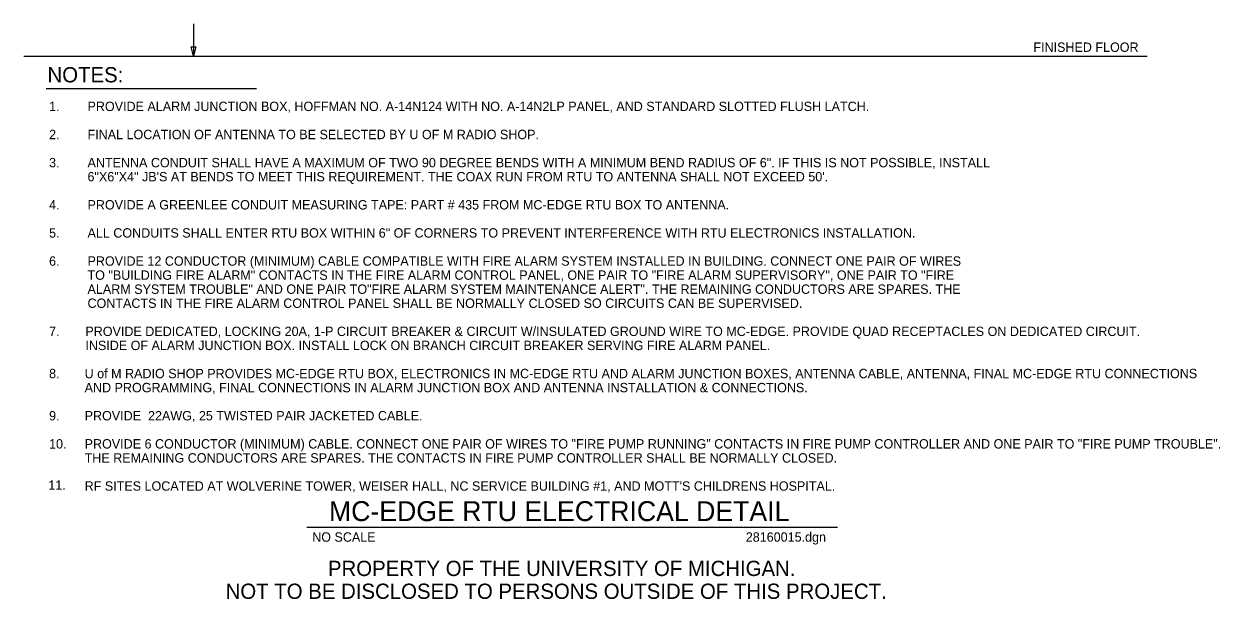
# Model space of a CAD drawing. Extents: x 10048.6 to 10135.3, y 10047.5 to 10138.5.
# Drawn here: x 10050.3 to 10135.3, y 10047.5 to 10088.4 of the extents above; entities that cross this region are included whole.
import ezdxf

# ---------------------------------------------------------------- set-up
doc = ezdxf.new("R2010")
doc.units = 0
for name, color, linetype in [('G-ANNO-CELL', 7, 'Continuous'), ('G-ANNO-TEXT', 7, 'Continuous'), ('G-DETL-PATT', 7, 'Continuous'), ('Level 3', 7, 'Continuous'), ('Level 52', 7, 'Continuous'), ('Level 60', 7, 'Continuous'), ('Level 63', 7, 'Continuous')]:
    doc.layers.add(name, color=color, linetype=linetype)

msp = doc.modelspace()

# ---------------------------------------------------------------- linework, layer by layer
at = {"layer": 'G-ANNO-CELL'}
msp.add_line((10051.862, 10083.812), (10066.824, 10083.812), dxfattribs=at)
at = {"layer": 'G-DETL-PATT'}
msp.add_line((10050.286, 10086.096), (10130.147, 10086.096), dxfattribs=at)
at = {"layer": 'Level 60'}
msp.add_line((10070.393, 10052.61), (10108.126, 10052.61), dxfattribs=at)
at = {"layer": 'Level 63'}
msp.add_line((10062.337, 10088.401), (10062.337, 10086.096), dxfattribs=at)
msp.add_lwpolyline([(10062.504, 10086.762), (10062.337, 10086.096), (10062.17, 10086.762)], close=True, dxfattribs=at)

# ---------------------------------------------------------------- texts
at = {"layer": 'G-ANNO-CELL'}
msp.add_text('NOTES: ', height=1.0833, dxfattribs=at).set_placement((10051.962, 10084.244))
at = {"layer": 'G-ANNO-TEXT'}
for s, height, p in [('PROVIDE ALARM JUNCTION BOX, HOFFMAN NO. A-14N124 WITH NO. A-14N2LP PANEL, AND STANDARD SLOTTED FLUSH LATCH.', 0.666667, (10054.808, 10082.204)), ('FINAL LOCATION OF ANTENNA TO BE SELECTED BY U OF M RADIO SHOP.', 0.66667, (10054.808, 10080.204)), ('ANTENNA CONDUIT SHALL HAVE A MAXIMUM OF TWO 90 DEGREE BENDS WITH A MINIMUM BEND RADIUS OF 6". IF THIS IS NOT POSSIBLE, INSTALL', 0.666667, (10054.808, 10078.204)), ('6"X6"X4" JB\'S AT BENDS TO MEET THIS REQUIREMENT. THE COAX RUN FROM RTU TO ANTENNA SHALL NOT EXCEED 50\'.', 0.666667, (10054.808, 10077.204)), ('PROVIDE A GREENLEE CONDUIT MEASURING TAPE: PART # 435 FROM MC-EDGE RTU BOX TO ANTENNA.', 0.66667, (10054.808, 10075.204)), ('ALL CONDUITS SHALL ENTER RTU BOX WITHIN 6" OF CORNERS TO PREVENT INTERFERENCE WITH RTU ELECTRONICS INSTALLATION.', 0.666667, (10054.808, 10073.204)), ('PROVIDE 12 CONDUCTOR (MINIMUM) CABLE COMPATIBLE WITH FIRE ALARM SYSTEM INSTALLED IN BUILDING. CONNECT ONE PAIR OF WIRES', 0.666667, (10054.808, 10071.204)), ('TO "BUILDING FIRE ALARM" CONTACTS IN THE FIRE ALARM CONTROL PANEL, ONE PAIR TO "FIRE ALARM SUPERVISORY", ONE PAIR TO "FIRE', 0.666667, (10054.808, 10070.204)), ('ALARM SYSTEM TROUBLE" AND ONE PAIR TO"FIRE ALARM SYSTEM MAINTENANCE ALERT". THE REMAINING CONDUCTORS ARE SPARES. THE', 0.666667, (10054.808, 10069.204)), ('CONTACTS IN THE FIRE ALARM CONTROL PANEL SHALL BE NORMALLY CLOSED SO CIRCUITS CAN BE SUPERVISED.', 0.66667, (10054.808, 10068.204)), ('11.', 0.6667, (10052.019, 10055.269)), ('PROPERTY OF THE UNIVERSITY OF MICHIGAN.', 1.08333, (10071.902, 10049.137)), ('NOT TO BE DISCLOSED TO PERSONS OUTSIDE OF THIS PROJECT.', 1.08333, (10064.627, 10047.512))]:
    msp.add_text(s, height=height, dxfattribs=at).set_placement(p)
at = {"layer": 'Level 3'}
msp.add_text('28160015.dgn', height=0.66667, dxfattribs=at).set_placement((10101.612, 10051.577))
at = {"layer": 'Level 52'}
msp.add_text('NO SCALE', height=0.6667, dxfattribs=at).set_placement((10070.783, 10051.575))
at = {"layer": 'Level 60'}
for s, height, p in [('FINISHED FLOOR', 0.66667, (10122.06, 10086.413)), ('PROVIDE DEDICATED, LOCKING 20A, 1-P CIRCUIT BREAKER & CIRCUIT W/INSULATED GROUND WIRE TO MC-EDGE. PROVIDE QUAD RECEPTACLES ON DEDICATED CIRCUIT.', 0.666667, (10054.656, 10066.204)), ('INSIDE OF ALARM JUNCTION BOX. INSTALL LOCK ON BRANCH CIRCUIT BREAKER SERVING FIRE ALARM PANEL.', 0.66667, (10054.656, 10065.204)), ('MC-EDGE RTU ELECTRICAL DETAIL     ', 1.41667, (10071.977, 10053.043))]:
    msp.add_text(s, height=height, dxfattribs=at).set_placement(p)
at = {"layer": 'Level 63'}
for s, height, p in [('1.', 0.6667, (10052.075, 10082.204)), ('2.', 0.6667, (10052.075, 10080.204)), ('3.', 0.6667, (10052.075, 10078.204)), ('4.', 0.6667, (10052.075, 10075.204)), ('5.', 0.6667, (10052.075, 10073.204)), ('6.', 0.6667, (10052.075, 10071.204)), ('7.', 0.6667, (10052.075, 10066.204)), ('8.', 0.6667, (10052.075, 10063.204)), ('U of M RADIO SHOP PROVIDES MC-EDGE RTU BOX, ELECTRONICS IN MC-EDGE RTU AND ALARM JUNCTION BOXES, ANTENNA CABLE, ANTENNA, FINAL MC-EDGE RTU CONNECTIONS', 0.666667, (10054.603, 10063.204)), ('AND PROGRAMMING, FINAL CONNECTIONS IN ALARM JUNCTION BOX AND ANTENNA INSTALLATION & CONNECTIONS.', 0.66667, (10054.603, 10062.204)), ('9.', 0.6667, (10052.075, 10060.204)), ('PROVIDE  22AWG, 25 TWISTED PAIR JACKETED CABLE.', 0.66667, (10054.603, 10060.204)), ('10.', 0.6667, (10052.075, 10058.204)), ('PROVIDE 6 CONDUCTOR (MINIMUM) CABLE. CONNECT ONE PAIR OF WIRES TO "FIRE PUMP RUNNING" CONTACTS IN FIRE PUMP CONTROLLER AND ONE PAIR TO "FIRE PUMP TROUBLE".', 0.666667, (10054.603, 10058.204)), ('THE REMAINING CONDUCTORS ARE SPARES. THE CONTACTS IN FIRE PUMP CONTROLLER SHALL BE NORMALLY CLOSED.', 0.66667, (10054.603, 10057.204)), ("RF SITES LOCATED AT WOLVERINE TOWER, WEISER HALL, NC SERVICE BUILDING #1, AND MOTT'S CHILDRENS HOSPITAL.", 0.666667, (10054.603, 10055.204))]:
    msp.add_text(s, height=height, dxfattribs=at).set_placement(p)

doc.saveas('drawing.dxf')
